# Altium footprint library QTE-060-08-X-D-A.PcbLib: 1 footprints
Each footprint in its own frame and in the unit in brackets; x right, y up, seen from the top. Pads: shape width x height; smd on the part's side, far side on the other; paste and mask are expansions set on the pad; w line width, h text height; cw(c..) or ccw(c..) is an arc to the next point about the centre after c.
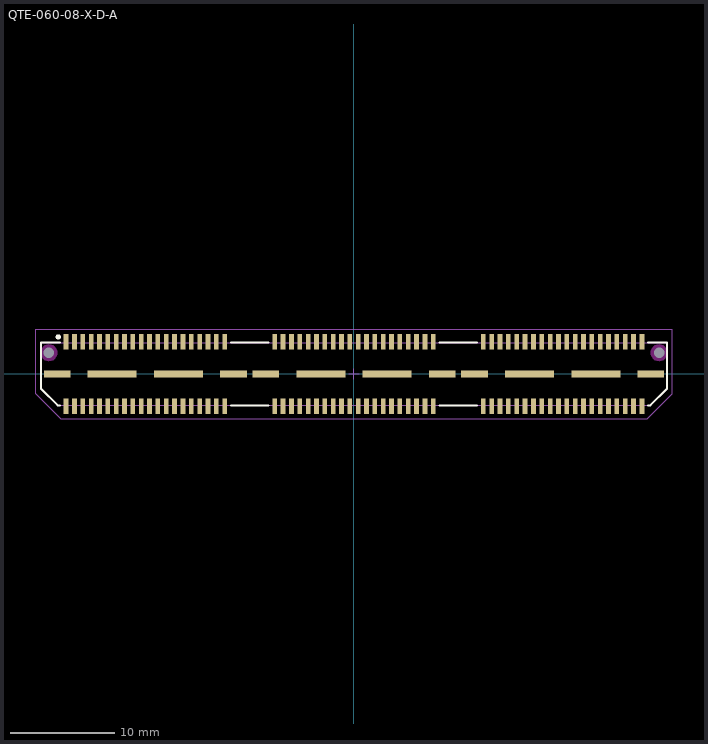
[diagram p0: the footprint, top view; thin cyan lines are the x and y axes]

## QTE-060-08-X-D-A [mm] "0.80mm pitch, 120 pin, high speed terminal strip"
height 4.27
pads (134):
  rect 0.45x1.45 smd mask+0: 1(-27.6,3.09) 2(-27.6,-3.09) 3(-26.8,3.09) 4(-26.8,-3.09) 5(-26,3.09) 6(-26,-3.09) 7(-25.2,3.09) 8(-25.2,-3.09) 9(-24.4,3.09) 10(-24.4,-3.09) 11(-23.6,3.09) 12(-23.6,-3.09) 13(-22.8,3.09) 14(-22.8,-3.09) 15(-22,3.09) 16(-22,-3.09) 17(-21.2,3.09) 18(-21.2,-3.09) 19(-20.4,3.09) 20(-20.4,-3.09) 21(-19.6,3.09) 22(-19.6,-3.09) 23(-18.8,3.09) 24(-18.8,-3.09) 25(-18,3.09) 26(-18,-3.09) 27(-17.2,3.09) 28(-17.2,-3.09) 29(-16.4,3.09) 30(-16.4,-3.09) 31(-15.6,3.09) 32(-15.6,-3.09) 33(-14.8,3.09) 34(-14.8,-3.09) 35(-14,3.09) 36(-14,-3.09) 37(-13.2,3.09) 38(-13.2,-3.09) 39(-12.4,3.09) 40(-12.4,-3.09) 41(-7.6,3.09) 42(-7.6,-3.09) 43(-6.8,3.09) 44(-6.8,-3.09) 45(-6,3.09) 46(-6,-3.09) 47(-5.2,3.09) 48(-5.2,-3.09) 49(-4.4,3.09) 50(-4.4,-3.09) 51(-3.6,3.09) 52(-3.6,-3.09) 53(-2.8,3.09) 54(-2.8,-3.09) 55(-2,3.09) 56(-2,-3.09) 57(-1.2,3.09) 58(-1.2,-3.09) 59(-0.4,3.09) 60(-0.4,-3.09) 61(0.4,3.09) 62(0.4,-3.09) 63(1.2,3.09) 64(1.2,-3.09) 65(2,3.09) 66(2,-3.09) 67(2.8,3.09) 68(2.8,-3.09) 69(3.6,3.09) 70(3.6,-3.09) 71(4.4,3.09) 72(4.4,-3.09) 73(5.2,3.09) 74(5.2,-3.09) 75(6,3.09) 76(6,-3.09) 77(6.8,3.09) 78(6.8,-3.09) 79(7.6,3.09) 80(7.6,-3.09) 81(12.4,3.09) 82(12.4,-3.09) 83(13.2,3.09) 84(13.2,-3.09) 85(14,3.09) 86(14,-3.09) 87(14.8,3.09) 88(14.8,-3.09) 89(15.6,3.09) 90(15.6,-3.09) 91(16.4,3.09) 92(16.4,-3.09) 93(17.2,3.09) 94(17.2,-3.09) 95(18,3.09) 96(18,-3.09) 97(18.8,3.09) 98(18.8,-3.09) 99(19.6,3.09) 100(19.6,-3.09) 101(20.4,3.09) 102(20.4,-3.09) 103(21.2,3.09) 104(21.2,-3.09) 105(22,3.09) 106(22,-3.09) 107(22.8,3.09) 108(22.8,-3.09) 109(23.6,3.09) 110(23.6,-3.09) 111(24.4,3.09) 112(24.4,-3.09) 113(25.2,3.09) 114(25.2,-3.09) 115(26,3.09) 116(26,-3.09) 117(26.8,3.09) 118(26.8,-3.09) 119(27.6,3.09) 120(27.6,-3.09)
  rect 2.55x0.65 smd mask+0: 121(-28.445,0) 124(-11.555,0) 125(-8.445,0) 128(8.445,0) 129(11.555,0) 132(28.445,0)
  rect 4.7x0.65 smd mask+0: 122(-23.175,0) 123(-16.825,0) 126(-3.175,0) 127(3.175,0) 130(16.825,0) 131(23.175,0)
  round 0.5 hole 1 unplated mask+0: 133(-29.24,2.04) 134(29.24,2.04)
Top Overlay:
  circle w0.25: c-28.35,3.55 r0.125
  lines w0.2: -28.2,-3 -28.4,-3 -30,-1.4 -30,3 -28.2,3 ; -11.8,-3 -8.2,-3 ; -11.8,3 -8.2,3 ; 8.2,-3 11.8,-3 ; 8.2,3 11.8,3 ; 28.2,-3 28.4,-3 30,-1.4 30,3 28.2,3
Keep-Out Layer:
  pour cut-out: 30.047,2.04 30.019,2.249 29.939,2.443 29.811,2.611 29.643,2.739 29.449,2.819 29.24,2.847 29.031,2.819 28.837,2.739 28.669,2.611 28.541,2.443 28.461,2.249 28.433,2.04 28.461,1.831 28.541,1.637 28.669,1.469 28.837,1.341 29.031,1.261 29.24,1.233 29.449,1.261 29.643,1.341 29.811,1.469 29.939,1.637 30.019,1.831
  pour cut-out: -28.433,2.04 -28.461,2.249 -28.541,2.443 -28.669,2.611 -28.837,2.739 -29.031,2.819 -29.24,2.847 -29.449,2.819 -29.643,2.739 -29.811,2.611 -29.939,2.443 -30.019,2.249 -30.047,2.04 -30.019,1.831 -29.939,1.637 -29.811,1.469 -29.643,1.341 -29.449,1.261 -29.24,1.233 -29.031,1.261 -28.837,1.341 -28.669,1.469 -28.541,1.637 -28.461,1.831
Mechanical 12:
  lines w0.001: -30,-1.4 -30,3 30,3 30,-1.4 28.4,-3 -28.4,-3 -30,-1.4
Mechanical 13:
  lines w0.1: -30,-1.4 -30,3 30,3 30,-1.4 28.4,-3 -28.4,-3 -30,-1.4
  text ".Designator" at 0.254,0.254 h1.52
Mechanical 15:
  lines w0.05: -0.5,0 0.5,0 ; 0,-0.5 0,0.5 ; -30.5,-1.9 -30.5,4.3 30.5,4.3 30.5,-1.9 28.1,-4.3 -28.1,-4.3 -30.5,-1.9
